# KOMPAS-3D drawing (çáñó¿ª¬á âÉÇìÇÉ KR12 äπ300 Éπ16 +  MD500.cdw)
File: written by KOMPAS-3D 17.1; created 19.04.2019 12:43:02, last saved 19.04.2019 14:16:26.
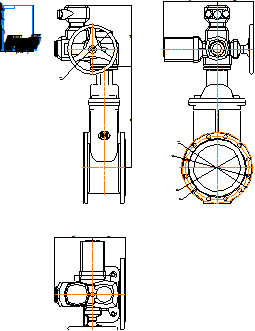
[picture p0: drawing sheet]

Sheet 1: A4, portrait

Title block, sheet 1: name: Задвижка ГРАНАР KR12 Ду300 Ру16 + / MD500; material: Внимание! Данный продукт является объектом авторского права ООО «Торговый Дом АДЛ». / Запрещается изменение, копирование, распространение / (в том числе путем копирования на другие сайты и ресурсы в Интернете) / или любое иное использование информации и объектов без предварительного / согласия правообладателя (ООО «Торговый Дом АДЛ»).; mass: 365,6; sheets: 1; organisation: ООО "Торговый дом АДЛ"; sheet format: A4; stored path: \\adlc.lan\data\АДЛ_ПКД\3D-модели\ADL production\Клиновые задвижки серии KR ГРАНАР\Клиновые задвижки KR12 с эл.приводами Смартгир\KOMPAS 2D\Задвижка ГРАНАР KR12 Ду300 Ру16 +  MD500.cdw

Views: Проекционный вид 3
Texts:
  user
Dimensions and other numbers on the sheet: 241,19; 208,81; 1:1; 1; 365,6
